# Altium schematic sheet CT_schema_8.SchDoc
size 147 x 119 mm
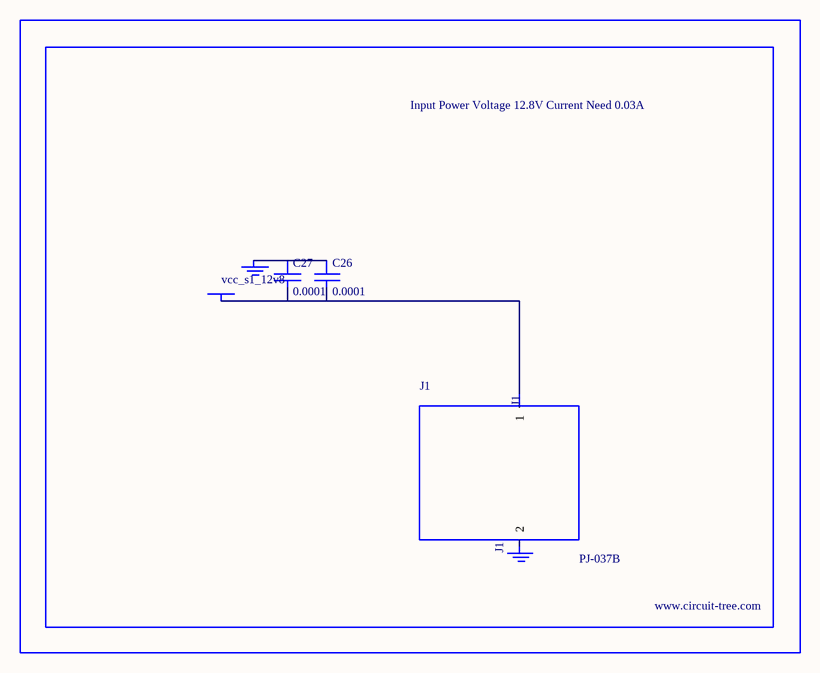
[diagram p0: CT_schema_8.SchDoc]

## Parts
BORDER7  (no value)
C26  0.0001  [EXV-9H]
C27  0.0001  [EXV-9H]
GND_INSTANCE_7_0  (no value)
GND_INSTANCE_7_1  (no value)
J1  PJ-037B  [PJ-037B_PACKAGE]
POWER_INSTANCE_7_0  vcc_s1_12v8

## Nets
NetC26_1: C26.1 C27.1 GND_INSTANCE_7_0.0(GND)
NetC26_2: C26.2 C27.2 J1.1 POWER_INSTANCE_7_0.0(PWR)

Not connected (* = marked no-connect by the designer): GND_INSTANCE_7_1 0(GND); J1 2

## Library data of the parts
BORDER7 = BORDER_PAGE7
C26 C27 = EDK107M035A9HAA
GND_INSTANCE_7_0 GND_INSTANCE_7_1 = GND
POWER_INSTANCE_7_0 = PWR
